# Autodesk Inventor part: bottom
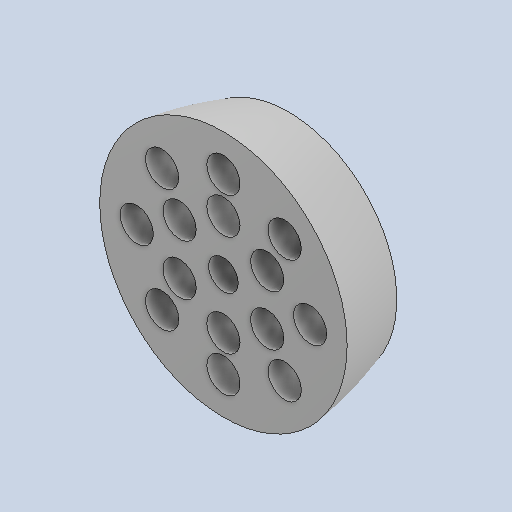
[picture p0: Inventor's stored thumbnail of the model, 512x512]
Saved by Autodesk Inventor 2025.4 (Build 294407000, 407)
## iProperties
Created: 2026-09
Part Number: bottom
Material: Generic
Document SubType Name: Modeling
Designer: AdminForWorker
Density: 1 g/cm^3
Appearance: Default
Title: bottom
Author: AdminForWorker
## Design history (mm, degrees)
feature "Body1"
body "Solid1"
